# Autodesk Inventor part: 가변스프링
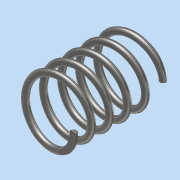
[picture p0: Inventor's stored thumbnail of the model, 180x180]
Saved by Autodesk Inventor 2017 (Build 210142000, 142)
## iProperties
Part Number: 가변스프링
Material: 스테인레스 스틸
Document SubType Name: Modeling
Designer: MRC
Density: 8 g/cm^3
Appearance: 반연마
Mass: 6.99701 g
Surface Area: 17.7559 cm^2
Volume: 0.874626 cm^3
Author: MRC
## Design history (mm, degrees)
sketch "스케치1"
  geometry: L1 (0, 0)-(0, 28.5); L2 (0, 0)-(9, 0); L3 (9, 28.5)-(0, 28.5); C1 r 1 at (9, 0)
  constraints: 6 end point, 1 centre point, 1 horizontal, 1 horizontal alignment, 1 vertical
  dimensions: "d0" = 28.5 distance of L1.start L1.end (derived); "d1" = 2 diameter of C1; "d3" = 18 diameter of L2.end L1
feature "코일1" sketch "스케치1" pitch "d4" = 10; turns "d6" = 5; dims "d5" = 28.5 (= d0), "d7" = 0, angle "d8" = 90 deg, angle "d9" = 90 deg, "d10" = 0, "d11" = 0
sketch "스케치2"
  geometry: L1 (28.5, 15)-(0, 15); L2 (0, 15)-(0, -15); L3 (0, -15)-(28.5, -15); L4 (28.5, -15)-(28.5, 15); 2 further points
  constraints: 8 end point, 2 parallel, 1 coincident, 1 horizontal, 1 midpoint, 1 perpendicular
  dimensions: "d12" = 30 distance of L3.end L1.start; "d16" = 28.5 distance of L1.start L1.end (= d0)
extrude "돌출1" sketch "스케치2" stored distance "d14" = 0; taper "d15" = 0 deg
node "솔리드1"
